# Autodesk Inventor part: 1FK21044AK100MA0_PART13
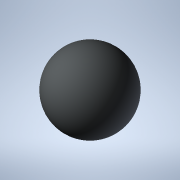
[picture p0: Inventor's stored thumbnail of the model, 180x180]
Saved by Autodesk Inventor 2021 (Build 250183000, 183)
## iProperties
Created: 2025-04
Part Number: 1FK21044AK100MA0_PART13
Material: Generic
Catalog Web Link: www.3dfindit.com
Description: -Servo synchronous motor
Document SubType Name: Modeling
Designer: psAdmin
Mass: 0.137258 g
Surface Area: 1.2868 cm^2
Volume: 0.137258 cm^3
Density: 1 g/cm^3
Appearance: PSOLRGB-212-217-219
Category: PARTsolutions
Title: 1FK21044AK100MA0_PART13
Author: Cadenas PARTsolutions
Comments: Servo synchronous motor
Sending System: PARTsolutions
Preprocessor: ST-DEVELOPER v19.3
PSOL_IDENT_0: {$CADENAS_DATA/23d-libs/siemens_ag/_cat_/5e/d8/1fk21044ak100ma0.prj},216 {VTYP=3D},{NB=1FK21044AK100
PSOL_IDENT_1: MA0_PART13},{LINA=1FK21044AK100MA0_PART13},{NN=1FK21044AK100MA0_PART13},{NOPRJ=TRUE},{DATE=19.08.202
PSOL_IDENT_2: 5 14:00:41},{GEOMDATE=30.07.2025 02:00:53},{VERSION=},{LINEID=10},{WBVAR=},{WBNUMERIC=}  {NB=1FK2104
PSOL_IDENT_3: 4AK100MA0_PART13},{LINA=1FK21044AK100MA0_PART13},{KT=DUMMY},{PREVIEW=../../../_pool_/cb/72/p_d211_xx
PSOL_IDENT_4: _00434j.png},{DESCSHORT=SIMOTICS S-1FK2 HD, SINAMICS S210 3AC 400V-480V, 0.95 Nm, 6000 rpm},{DESCLON
PSOL_IDENT_5: G=SIMOTICS S-1FK2 HD servo motor M0=1.27 Nm; PN = 0.6 kW at nN=6000 rpm (380-480 V); PN = 0.4 kW at
PSOL_IDENT_6: nN=3000 rpm (200-240 V); with holding brake; degree of protection IP64; cylindrical shaft D19x40mm;
PSOL_IDENT_7: absolute encoder 22-bit + 12-bit multiturn (encoder AM22DQC); with OCC interface; plug size M17, rot
PSOL_IDENT_8: atable; SIMOTICS S-1FK2 servomotorfor a wide range of uses in industrial environments. SIMOTICS S‑1F
PSOL_IDENT_9: K2 servomotors are compact synchronous motors with a high dynamic performance that set themselves ap
PSOL_IDENT_10: art as a result of their high power density, degree of protection and overload capability. The motor
PSOL_IDENT_11: s are available in two variants: as High Dynamic variant (highest dynamic performance as a result of
PSOL_IDENT_12: the low intrinsic moment of inertia for applications demanding a high dynamic performance with low
PSOL_IDENT_13: moved masses) - and as Compact variant (precise and stable closed-loop control for medium up to larg
PSOL_IDENT_14: e moved masses as a result of a medium intrinsic moment of inertia). SIMOTICSS‑1FK2 servomotors full
PSOL_IDENT_15: y exploit their strengths in a system with the SINAMICSS210 frequency converter and simple connectio
PSOL_IDENT_16: n using the one cable connection (OCC). Advantages include the short control and positioning times,
PSOL_IDENT_17: fast and precise correction of disturbing quantities as well as stable control with a high dynamic p
PSOL_IDENT_18: erformance. The servo motors can be configured to address a wide range of requirements. For example
PSOL_IDENT_19: with and without holding brake, IP64 or IP65 degree of protection, singleturn or multiturn absolute
PSOL_IDENT_20: encoders - to name just a few. Further, the servomotors are available in different shaft heights ext
PSOL_IDENT_21: ending from 20 to 100. A shaft sealing ring is available to achieve an IP65 degree of protection and
PSOL_IDENT_22: for subsequent mounting at the motor or as spare part. SIMOTICS - the optimum motor for each and ev
PSOL_IDENT_23: ery motion control application.},{INTNO=804766910005},{SUPPLIERALTNO=1FK2104-4AK10-0MA0},{MANUID=1FK
PSOL_IDENT_24: 21044AK100MA0},{MANUNAME=Siemens},{MANUTYPEDESC=Synchronous motor 1FK2-HD 1,27 Nm},{AAU732=SIMOTICS}
PSOL_IDENT_25: ,{AAO057=S-1FK2},{AAU734=SIMOTICS S-1FK2 HD servo motor M0=1.27 Nm; PN = 0.6 kW at nN=6000 rpm (380-
PSOL_IDENT_26: 480 V); PN = 0.4 kW at nN=3000 rpm (200-240 V); with holding brake; degree of protection IP64; cylin
PSOL_IDENT_27: drical shaft D19x40mm; absolute encoder 22-bit + 12-bit multiturn (encoder AM22DQC); with OCC interf
PSOL_IDENT_28: ace; plug size M17, rotatable;},{AAW338=Synchronous motor 1FK2-HD 1,27 Nm},{AAO742=SIMOTICS},{AAO663=
PSOL_IDENT_29: 4042948691076},{NOCUPEROU=1},{PRICEQUANTITY=1},{QUANTITYMIN=1},{QUANTITYINT=1},{CTN=85015100},{COO=D
PSOL_IDENT_30: E},{AAO676=1FK2104-4AK10-0MA0},{AAO677=Siemens AG},{ORDERUNIT=C62},{CONTENTUNIT=C62}
NB: 1FK21044AK100MA0_PART13
NT: Servo synchronous motor
NBSYN: $MANUID._PART13
LINA: 1FK21044AK100MA0_PART13
CATALOG: SIEMENS
PREVIEW: ../../../_pool_/cb/72/p_d211_xx_00434j.png
DESCSHORT: SIMOTICS S-1FK2 HD, SINAMICS S210 3AC 400V-480V, 0.95 Nm, 6000 rpm
DESCLONG: SIMOTICS S-1FK2 HD servo motor M0=1.27 Nm; PN = 0.6 kW at nN=6000 rpm (380-480 V); PN = 0.4 kW at nN=3000 rpm (200-240 V); with holding brake; degree of protect
INTNO: 804766910005
SUPPLIERALTNO: 1FK2104-4AK10-0MA0
MANUID: 1FK21044AK100MA0
MANUNAME: Siemens
MANUTYPEDESC: Synchronous motor 1FK2-HD 1,27 Nm
AAU732: SIMOTICS
AAO057: S-1FK2
AAU734: SIMOTICS S-1FK2 HD servo motor M0=1.27 Nm; PN = 0.6 kW at nN=6000 rpm (380-480 V); PN = 0.4 kW at nN=3000 rpm (200-240 V); with holding brake; degree of protect
AAW338: Synchronous motor 1FK2-HD 1,27 Nm
AAO742: SIMOTICS
AAO663: 4042948691076.0
NOCUPEROU: 1
PRICEQUANTITY: 1
QUANTITYMIN: 1
QUANTITYINT: 1
CTN: 85015100
COO: DE
ARTICLENO: 1FK21044AK100MA0_PART13
BOMINFO: 1FK21044AK100MA0_PART13
CREATOR: CADENAS GmbH
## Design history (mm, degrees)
feature "2025_04_17_15_35_41_0968"
body "Solid1"
